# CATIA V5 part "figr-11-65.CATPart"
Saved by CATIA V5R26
Part number: Part1
Bounding box of the stored display mesh (mm): x -54 to 54, y -91.936 to 93.838, z -12.649 to 110.643
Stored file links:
  D:\_Deepak\CATIA\CATIA V5-6R2016_Deepak\Resources\Part files\Partfiles\c11_catia_v5_6r2016_prt\figr-11-65.CATPart
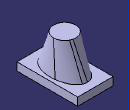
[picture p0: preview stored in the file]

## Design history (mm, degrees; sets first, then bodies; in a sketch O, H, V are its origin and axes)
Set1
  Loft1: Sections (Sketch4; Sketch3)
Body1 (main body)
  Sketch1 on yz-plane, origin (0, 0, 0), H (0, 1, 0), V (0, 0, 1)
    point P1 (93.8379, 11.643)
    line L1 (93.8379, 11.643) -> (93.8379, -12.6487)
    line L2 (93.8379, -12.6487) -> (-91.9362, -12.6487)
    line L3 (-91.9362, -12.6487) -> (-91.9362, 11.643)
    line L4 (-91.9362, 11.643) -> (93.8379, 11.643)
    point P5 (93.8379, 11.643)
    vertical: L1 V, L3 V
    horizontal: L2 H, L4 H
    coincidence: P5 P1
  Pad1: profile Sketch1, direction (1, 0, 0), length 54, mirrored extent
  Sketch2 on face of Pad1, origin (0, 0, 11.643), H (1, 0, 0), V (0, 1, 0)
    circle A1 centre (0, 0) radius 16.7533
    point P1 (16.7533, 0)
    coincidence: A1 P1, P1 H
  Pad2: profile Sketch2, direction (0, 0, 1), length 99
  SewSurface1: SewingRemoveFace face of Pad2, SplitPlane Loft1
  Sketch3 on face of Pad2, origin (0, 0, 110.643), H (1, 0, 0), V (0, 1, 0)
    point P1 (0, 42.8937)
    point P2 (33.9651, 0)
    projected circle E1 centre (0, 0) radius 16.7533 from edge [face of Pad2 | face of Pad2]
    circle A1 centre (0, 0) radius 33.9651
    point P3 (0, 33.9651)
    coincidence: P1 V, P2 H, A1 P2, A1 P3, P3 V
  Sketch4 on face of Pad1, origin (0, 0, 11.643), H (1, 0, 0), V (0, 1, 0)
    ellipse A1 centre (0, 0) semi-axes 69.9141, 43.1918 rotation 90
    point P1 (0, 69.9141)
    point P2 (43.1918, 0)
    coincidence: P1 V, P2 H, A1 P1, A1 P2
